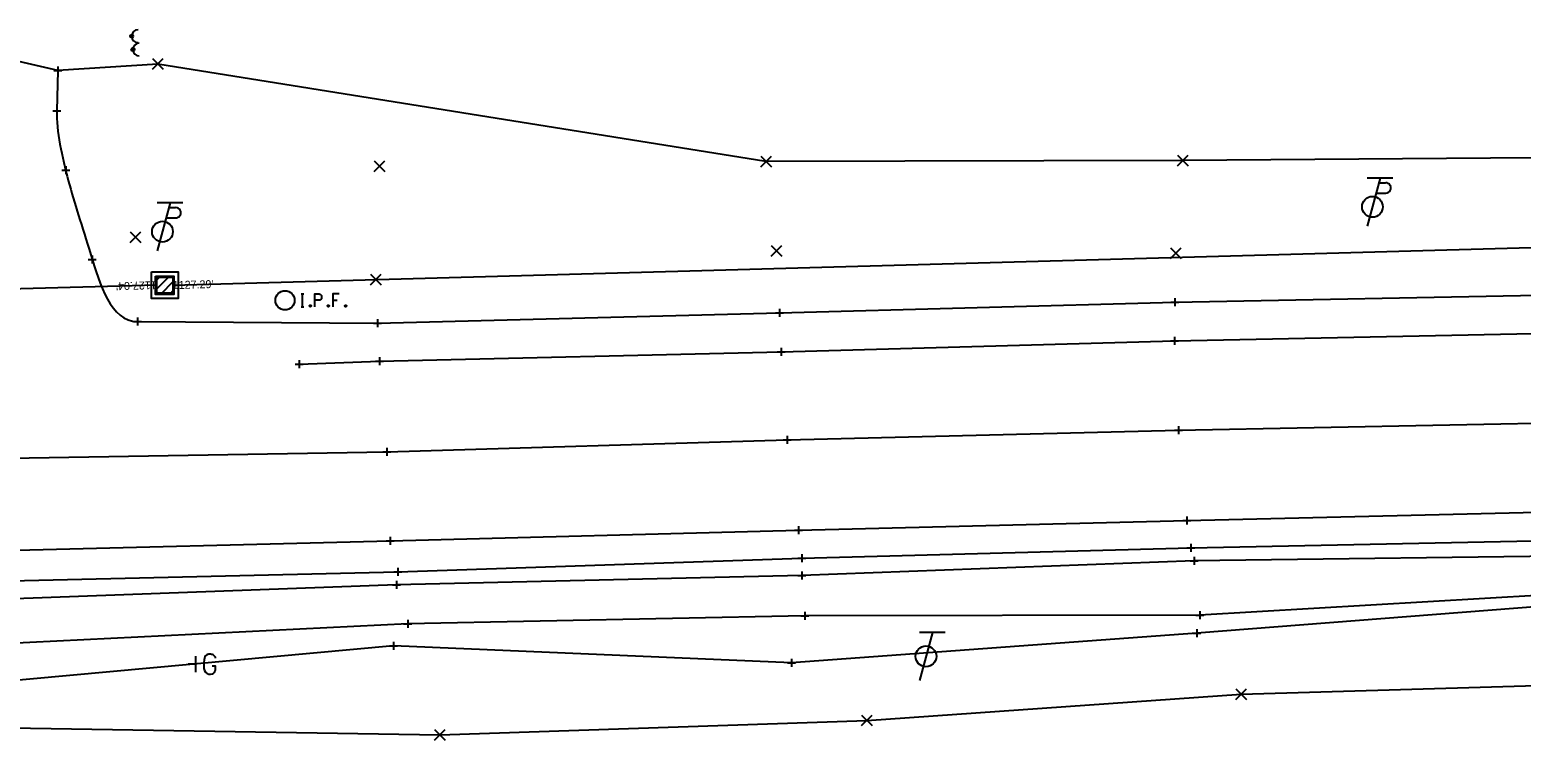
# Model space of a CAD drawing. Extents: x 2402028 to 2407435, y 498611 to 499105.
# Drawn here: x 2404240.4 to 2404426.7, y 498663.4 to 498752.2 of the extents above; entities that cross this region are included whole.
import ezdxf

# ---------------------------------------------------------------- set-up
doc = ezdxf.new("R2010")
doc.units = 0
for name, color, linetype in [('DR_X_Ditch', 7, 'Continuous'), ('DR_X_Storm_Sewer', 7, 'Continuous'), ('PV_X_COP', 7, 'Continuous'), ('PV_X_EOP', 7, 'Continuous'), ('PV_X_Shoulder', 7, 'Continuous'), ('RW_X_CL_1000_Bearings', 7, 'Continuous'), ('RW_X_CL_1000_Cardinal_Points', 7, 'Continuous'), ('RW_X_CL_1000_Distances', 7, 'Continuous'), ('RW_X_CL_100_Distances', 7, 'Continuous'), ('RW_X_CL_100_Stations', 7, 'Continuous'), ('RW_X_CL_500_Bearings', 7, 'Continuous'), ('RW_X_CL_500_Cardinal_Points', 7, 'Continuous'), ('RW_X_CL_500_Stations', 7, 'Continuous'), ('SC_Scratch1', 7, 'Continuous'), ('SV_X_Break_Lines', 7, 'Continuous'), ('SV_X_Terrain_Boundary', 7, 'Continuous')]:
    doc.layers.add(name, color=color, linetype=linetype)

msp = doc.modelspace()

# ---------------------------------------------------------------- linework, layer by layer
at = {"layer": 'DR_X_Ditch'}
msp.add_lwpolyline([(2404533.24, 498683.6), (2404485.13, 498682.32), (2404436.39, 498681.96), (2404386.54, 498679.04), (2404337.17, 498678.98), (2404287.56, 498677.96), (2404236.98, 498675.49), (2404187.96, 498674.52), (2404135.48, 498673.31), (2404086.4, 498671.8), (2404053.2, 498673.48), (2404047.02, 498674.14)], dxfattribs=at)
at = {"layer": 'DR_X_Storm_Sewer'}
for p, q in [((2404258.21, 498720.31), (2404616.99, 498730.22)), ((2404256.21, 498720.31), (2404167.84, 498717.88))]:
    msp.add_line(p, q, dxfattribs=at)
at = {"layer": 'PV_X_COP'}
msp.add_lwpolyline([(2403985.57, 498692.23), (2404036.54, 498693.02), (2404085.82, 498695.1), (2404135.38, 498696.42), (2404186.49, 498697.31), (2404235.26, 498698.66), (2404284.95, 498699.47), (2404334.96, 498700.99), (2404383.89, 498702.2), (2404434.73, 498703.18), (2404484.39, 498704.35), (2404533.55, 498705.6)], dxfattribs=at)
at = {"layer": 'PV_X_EOP'}
for points in [[(2404274.02, 498710.44), (2404284.04, 498710.8), (2404334.24, 498711.98), (2404383.36, 498713.34), (2404434.3, 498714.39), (2404483.69, 498715.86), (2404533.18, 498717.39)], [(2403985.56, 498681.24), (2404036.04, 498682.2), (2404086.24, 498683.82), (2404136.5, 498684.82), (2404187.36, 498686.15), (2404235.32, 498687.11), (2404285.36, 498688.37), (2404336.4, 498689.7), (2404384.93, 498690.9), (2404435.67, 498692.09), (2404485.01, 498693.22), (2404533.25, 498694.59)]]:
    msp.add_lwpolyline(points, dxfattribs=at)
at = {"layer": 'PV_X_Shoulder'}
for p, q in [((2404243.83, 498747.15), (2404243.72, 498742.11)), ((2404383.4, 498718.17), (2404433.92, 498719.18)), ((2404334, 498716.84), (2404383.4, 498718.17)), ((2404253.79, 498715.76), (2404283.79, 498715.54)), ((2404283.79, 498715.54), (2404334, 498716.84))]:
    msp.add_line(p, q, dxfattribs=at)
msp.add_lwpolyline([(2403986.56, 498676.91), (2404036.95, 498678.51), (2404086.64, 498679.64), (2404136.45, 498680.88), (2404187.63, 498682.62), (2404236.08, 498683.33), (2404286.33, 498684.49), (2404336.81, 498686.17), (2404385.43, 498687.48), (2404436.29, 498688.5), (2404485.75, 498689.82), (2404533.69, 498691.17)], dxfattribs=at)
msp.add_open_spline([(2404243.72, 498742.11), (2404243.66, 498739.6), (2404245.07, 498733.1), (2404247.73, 498725.12), (2404250.47, 498715.78), (2404253.79, 498715.76)], degree=3, dxfattribs=at)
at = {"layer": 'RW_X_CL_1000_Bearings'}
for p, q in [((2404256.06, 498719.69), (2404257.82, 498721.45)), ((2404256.06, 498720.82), (2404256.69, 498721.45)), ((2404256.66, 498719.16), (2404258.35, 498720.85)), ((2404257.79, 498719.16), (2404258.35, 498719.72))]:
    msp.add_line(p, q, dxfattribs=at)
for points in [[(2404255.54, 498721.97), (2404258.87, 498721.97), (2404258.87, 498718.64), (2404255.54, 498718.64)], [(2404256.06, 498721.45), (2404258.35, 498721.45), (2404258.35, 498719.16), (2404256.06, 498719.16)], [(2404256.21, 498721.31), (2404258.21, 498721.31), (2404258.21, 498719.31), (2404256.21, 498719.31)]]:
    msp.add_lwpolyline(points, close=True, dxfattribs=at)
at = {"layer": 'RW_X_CL_1000_Cardinal_Points'}
for p, q in [((2404257.21, 498721.97), (2404257.21, 498721.97)), ((2404257.21, 498721.31), (2404257.21, 498721.31)), ((2404256.21, 498720.31), (2404256.21, 498720.31)), ((2404257.21, 498720.31), (2404257.21, 498720.31)), ((2404257.21, 498720.31), (2404257.21, 498720.31)), ((2404257.21, 498720.31), (2404257.21, 498720.31)), ((2404257.21, 498719.31), (2404257.21, 498719.31)), ((2404258.21, 498720.31), (2404258.21, 498720.31)), ((2404257.21, 498718.64), (2404257.21, 498718.64))]:
    msp.add_line(p, q, dxfattribs=at)
at = {"layer": 'RW_X_CL_1000_Distances'}
for p, q in [((2404353.13, 498676.91), (2404351.52, 498670.91)), ((2404354.73, 498676.91), (2404351.53, 498676.91))]:
    msp.add_line(p, q, dxfattribs=at)
msp.add_circle((2404352.32, 498673.91), 1.3, dxfattribs=at)
at = {"layer": 'RW_X_CL_100_Distances'}
for p, q in [((2404261.08, 498672.93), (2404260.13, 498672.93)), ((2404261.08, 498671.93), (2404261.08, 498673.93))]:
    msp.add_line(p, q, dxfattribs=at)
msp.add_lwpolyline([(2404263.55, 498673.69), (2404263.53, 498673.79), (2404263.47, 498673.89), (2404263.38, 498673.99), (2404263.24, 498674.1), (2404263.14, 498674.14), (2404263.06, 498674.16), (2404262.94, 498674.18), (2404262.71, 498674.18), (2404262.61, 498674.16), (2404262.55, 498674.14), (2404262.47, 498674.1), (2404262.31, 498673.99), (2404262.22, 498673.85), (2404262.16, 498673.69), (2404262.12, 498673.47), (2404262.08, 498673.16), (2404262.08, 498672.75), (2404262.1, 498672.41), (2404262.18, 498672.15), (2404262.29, 498671.92), (2404262.39, 498671.84), (2404262.51, 498671.76), (2404262.73, 498671.68), (2404262.94, 498671.68), (2404263.16, 498671.72), (2404263.24, 498671.76), (2404263.32, 498671.8), (2404263.4, 498671.88), (2404263.47, 498672), (2404263.55, 498672.17), (2404263.55, 498672.67), (2404263.14, 498672.67)], dxfattribs=at)
at = {"layer": 'RW_X_CL_100_Stations'}
for points in [[(2404274.24, 498719.21), (2404274.59, 498719.21)], [(2404274.42, 498717.61), (2404274.42, 498719.21)], [(2404275.98, 498717.61), (2404275.98, 498719.21), (2404276.51, 498719.21), (2404276.57, 498719.2), (2404276.64, 498719.17), (2404276.68, 498719.15), (2404276.71, 498719.12), (2404276.75, 498719.06), (2404276.79, 498719), (2404276.81, 498718.89), (2404276.81, 498718.74), (2404276.8, 498718.69), (2404276.78, 498718.62), (2404276.73, 498718.53), (2404276.69, 498718.49), (2404276.66, 498718.47), (2404276.6, 498718.44), (2404276.51, 498718.43), (2404275.98, 498718.43)], [(2404278.99, 498719.21), (2404278.23, 498719.21), (2404278.23, 498717.61)], [(2404274.24, 498717.61), (2404274.59, 498717.61)], [(2404275.38, 498717.82), (2404275.43, 498717.82), (2404275.47, 498717.8), (2404275.5, 498717.75), (2404275.5, 498717.69), (2404275.47, 498717.64), (2404275.43, 498717.61), (2404275.38, 498717.61), (2404275.34, 498717.64), (2404275.31, 498717.69), (2404275.31, 498717.75), (2404275.34, 498717.8), (2404275.38, 498717.82)], [(2404277.63, 498717.82), (2404277.68, 498717.82), (2404277.71, 498717.8), (2404277.75, 498717.75), (2404277.75, 498717.69), (2404277.71, 498717.64), (2404277.68, 498717.61), (2404277.63, 498717.61), (2404277.59, 498717.64), (2404277.56, 498717.69), (2404277.56, 498717.75), (2404277.59, 498717.8), (2404277.63, 498717.82)], [(2404278.23, 498718.43), (2404278.77, 498718.43)], [(2404279.77, 498717.82), (2404279.83, 498717.82), (2404279.86, 498717.8), (2404279.9, 498717.75), (2404279.9, 498717.69), (2404279.86, 498717.64), (2404279.83, 498717.61), (2404279.77, 498717.61), (2404279.74, 498717.64), (2404279.71, 498717.69), (2404279.71, 498717.75), (2404279.74, 498717.8), (2404279.77, 498717.82)]]:
    msp.add_lwpolyline(points, dxfattribs=at)
msp.add_circle((2404272.23, 498718.41), 1.2, dxfattribs=at)
at = {"layer": 'RW_X_CL_500_Bearings'}
for p, q in [((2404243.33, 498747.15), (2404244.33, 498747.15)), ((2404243.83, 498747.65), (2404243.83, 498746.65)), ((2404243.83, 498747.15), (2404243.83, 498747.15)), ((2404243.22, 498742.11), (2404244.22, 498742.11)), ((2404243.72, 498742.61), (2404243.72, 498741.61)), ((2404243.72, 498742.11), (2404243.72, 498742.11)), ((2404244.33, 498734.68), (2404245.33, 498734.68)), ((2404244.83, 498735.18), (2404244.83, 498734.18)), ((2404244.83, 498734.68), (2404244.83, 498734.68)), ((2404247.65, 498723.52), (2404248.65, 498723.52)), ((2404248.15, 498724.02), (2404248.15, 498723.02)), ((2404248.15, 498723.52), (2404248.15, 498723.52)), ((2404334, 498717.34), (2404334, 498716.34)), ((2404382.9, 498718.17), (2404383.9, 498718.17)), ((2404383.4, 498718.67), (2404383.4, 498717.67)), ((2404383.4, 498718.17), (2404383.4, 498718.17)), ((2404253.29, 498715.76), (2404254.29, 498715.76)), ((2404253.79, 498716.26), (2404253.79, 498715.26)), ((2404253.79, 498715.76), (2404253.79, 498715.76)), ((2404283.29, 498715.54), (2404284.29, 498715.54)), ((2404283.79, 498716.04), (2404283.79, 498715.04)), ((2404283.79, 498715.54), (2404283.79, 498715.54)), ((2404333.5, 498716.84), (2404334.5, 498716.84)), ((2404334, 498716.84), (2404334, 498716.84)), ((2404382.86, 498713.34), (2404383.86, 498713.34)), ((2404383.36, 498713.84), (2404383.36, 498712.84)), ((2404383.36, 498713.34), (2404383.36, 498713.34)), ((2404333.74, 498711.98), (2404334.74, 498711.98)), ((2404334.24, 498712.48), (2404334.24, 498711.48)), ((2404334.24, 498711.98), (2404334.24, 498711.98)), ((2404273.52, 498710.44), (2404274.52, 498710.44)), ((2404274.02, 498710.94), (2404274.02, 498709.94)), ((2404274.02, 498710.44), (2404274.02, 498710.44)), ((2404283.54, 498710.8), (2404284.54, 498710.8)), ((2404284.04, 498711.3), (2404284.04, 498710.3)), ((2404284.04, 498710.8), (2404284.04, 498710.8)), ((2404383.39, 498702.2), (2404384.39, 498702.2)), ((2404383.89, 498702.7), (2404383.89, 498701.7)), ((2404383.89, 498702.2), (2404383.89, 498702.2)), ((2404334.46, 498700.99), (2404335.46, 498700.99)), ((2404334.96, 498701.49), (2404334.96, 498700.49)), ((2404334.96, 498700.99), (2404334.96, 498700.99)), ((2404284.45, 498699.47), (2404285.45, 498699.47)), ((2404284.95, 498699.97), (2404284.95, 498698.97)), ((2404284.95, 498699.47), (2404284.95, 498699.47)), ((2404384.43, 498690.9), (2404385.43, 498690.9)), ((2404384.93, 498691.4), (2404384.93, 498690.4)), ((2404384.93, 498690.9), (2404384.93, 498690.9)), ((2404335.9, 498689.7), (2404336.9, 498689.7)), ((2404336.4, 498690.2), (2404336.4, 498689.2)), ((2404336.4, 498689.7), (2404336.4, 498689.7)), ((2404284.86, 498688.37), (2404285.86, 498688.37)), ((2404285.36, 498688.87), (2404285.36, 498687.87)), ((2404285.36, 498688.37), (2404285.36, 498688.37)), ((2404384.93, 498687.48), (2404385.93, 498687.48)), ((2404385.43, 498687.98), (2404385.43, 498686.98)), ((2404385.43, 498687.48), (2404385.43, 498687.48)), ((2404336.31, 498686.17), (2404337.31, 498686.17)), ((2404336.81, 498686.67), (2404336.81, 498685.67)), ((2404336.81, 498686.17), (2404336.81, 498686.17)), ((2404385.31, 498685.86), (2404386.31, 498685.86)), ((2404385.81, 498686.36), (2404385.81, 498685.36)), ((2404385.81, 498685.86), (2404385.81, 498685.86)), ((2404285.83, 498684.49), (2404286.83, 498684.49)), ((2404286.33, 498684.99), (2404286.33, 498683.99)), ((2404286.33, 498684.49), (2404286.33, 498684.49)), ((2404336.29, 498684.01), (2404337.29, 498684.01)), ((2404336.79, 498684.51), (2404336.79, 498683.51)), ((2404336.79, 498684.01), (2404336.79, 498684.01)), ((2404285.66, 498682.85), (2404286.66, 498682.85)), ((2404286.16, 498683.35), (2404286.16, 498682.35)), ((2404286.16, 498682.85), (2404286.16, 498682.85)), ((2404287.06, 498677.96), (2404288.06, 498677.96)), ((2404287.56, 498678.46), (2404287.56, 498677.46)), ((2404287.56, 498677.96), (2404287.56, 498677.96)), ((2404336.67, 498678.98), (2404337.67, 498678.98)), ((2404337.17, 498679.48), (2404337.17, 498678.48)), ((2404337.17, 498678.98), (2404337.17, 498678.98)), ((2404386.04, 498679.04), (2404387.04, 498679.04)), ((2404386.54, 498679.54), (2404386.54, 498678.54)), ((2404386.54, 498679.04), (2404386.54, 498679.04)), ((2404385.68, 498676.8), (2404386.68, 498676.8)), ((2404386.18, 498677.3), (2404386.18, 498676.3)), ((2404386.18, 498676.8), (2404386.18, 498676.8)), ((2404285.3, 498675.24), (2404286.3, 498675.24)), ((2404285.8, 498675.74), (2404285.8, 498674.74)), ((2404285.8, 498675.24), (2404285.8, 498675.24)), ((2404335.03, 498673.1), (2404336.03, 498673.1)), ((2404335.53, 498673.6), (2404335.53, 498672.6)), ((2404335.53, 498673.1), (2404335.53, 498673.1))]:
    msp.add_line(p, q, dxfattribs=at)
at = {"layer": 'RW_X_CL_500_Cardinal_Points'}
for p, q in [((2404410.66, 498733.7), (2404407.46, 498733.7)), ((2404409.06, 498733.7), (2404407.46, 498727.7)), ((2404408.9, 498733.1), (2404409.75, 498733.1)), ((2404259.48, 498730.6), (2404256.28, 498730.6)), ((2404257.88, 498730.6), (2404256.28, 498724.6)), ((2404408.56, 498731.82), (2404409.75, 498731.82)), ((2404257.38, 498728.72), (2404258.57, 498728.72)), ((2404257.72, 498730), (2404258.57, 498730))]:
    msp.add_line(p, q, dxfattribs=at)
for centre, radius in [((2404253.08, 498751.43), 0.2), ((2404253.23, 498749.76), 0.2), ((2404408.1, 498730.1), 1.3), ((2404256.92, 498727), 1.3)]:
    msp.add_circle(centre, radius, dxfattribs=at)
for centre, radius, start, end in [((2404253.88, 498751.43), 0.8, 90, 270), ((2404254.03, 498749.76), 0.8, 90, 270), ((2404409.77, 498732.46), 0.638, 268.8767, 91.1233), ((2404258.59, 498729.36), 0.638, 268.8767, 91.1233)]:
    msp.add_arc(centre, radius, start, end, dxfattribs=at)
at = {"layer": 'RW_X_CL_500_Stations'}
for p, q in [((2404255.67, 498747.29), (2404257, 498748.62)), ((2404255.67, 498748.62), (2404257, 498747.29)), ((2404283.37, 498734.51), (2404284.7, 498735.85)), ((2404283.37, 498735.85), (2404284.7, 498734.51)), ((2404331.67, 498735.08), (2404333, 498736.42)), ((2404331.67, 498736.42), (2404333, 498735.08)), ((2404383.75, 498735.23), (2404385.09, 498736.57)), ((2404383.75, 498736.57), (2404385.09, 498735.23)), ((2404252.9, 498725.66), (2404254.23, 498726.99)), ((2404252.9, 498726.99), (2404254.23, 498725.66)), ((2404332.99, 498723.93), (2404334.32, 498725.27)), ((2404332.99, 498725.27), (2404334.32, 498723.93)), ((2404382.87, 498723.64), (2404384.2, 498724.97)), ((2404382.87, 498724.97), (2404384.2, 498723.64)), ((2404282.91, 498720.37), (2404284.24, 498721.7)), ((2404282.91, 498721.7), (2404284.24, 498720.37)), ((2404391.04, 498668.51), (2404392.37, 498669.85)), ((2404391.04, 498669.85), (2404392.37, 498668.51)), ((2404344.25, 498665.25), (2404345.58, 498666.58)), ((2404344.25, 498666.58), (2404345.58, 498665.25)), ((2404290.92, 498663.43), (2404292.25, 498664.77)), ((2404290.92, 498664.77), (2404292.25, 498663.43))]:
    msp.add_line(p, q, dxfattribs=at)
at = {"layer": 'SV_X_Break_Lines'}
for points in [[(2404534.29, 498688.61), (2404486.42, 498687.58), (2404437.42, 498686.5), (2404385.81, 498685.86), (2404336.79, 498684.01), (2404286.16, 498682.85), (2404233.91, 498680.95), (2404188.17, 498680.27), (2404137.24, 498679.18), (2404087.21, 498677.64), (2404055.25, 498678.14)], [(2404534.06, 498678.67), (2404487.14, 498679.19), (2404435.91, 498680.7), (2404386.18, 498676.8), (2404335.53, 498673.1), (2404285.8, 498675.24), (2404235.32, 498670.62), (2404187.68, 498672.55), (2404137.13, 498671.73), (2404087.36, 498666.97), (2404054.4, 498671.14), (2404059.39, 498667.3)]]:
    msp.add_lwpolyline(points, dxfattribs=at)
at = {"layer": 'SV_X_Terrain_Boundary'}
msp.add_lwpolyline([(2404232.73, 498665.07), (2404291.58, 498664.1), (2404344.92, 498665.91), (2404391.7, 498669.18), (2404444.29, 498670.72), (2404496.69, 498669.08), (2404540.12, 498669.09), (2404534.06, 498678.67), (2404533.24, 498683.6), (2404534.29, 498688.61), (2404533.69, 498691.17), (2404533.55, 498705.6), (2404533.43, 498721.84), (2404533.43, 498729.25), (2404533.22, 498738.21), (2404483.83, 498737.93), (2404433.86, 498736.27), (2404384.42, 498735.9), (2404332.33, 498735.75), (2404256.33, 498747.95), (2404243.83, 498747.15), (2404234.24, 498749.33)], dxfattribs=at)

# ---------------------------------------------------------------- texts
at = {"layer": 'SC_Scratch1'}
for s, rotation, p in [("1127.04'", 181.5699, (2404256.19, 498720.81)), ("1127.29'", 1.5835, (2404258.22, 498719.81))]:
    msp.add_text(s, height=1, rotation=rotation, dxfattribs=at).set_placement(p)

doc.saveas('drawing.dxf')
